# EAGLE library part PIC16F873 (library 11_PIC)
MICROCONTROLLER flash type
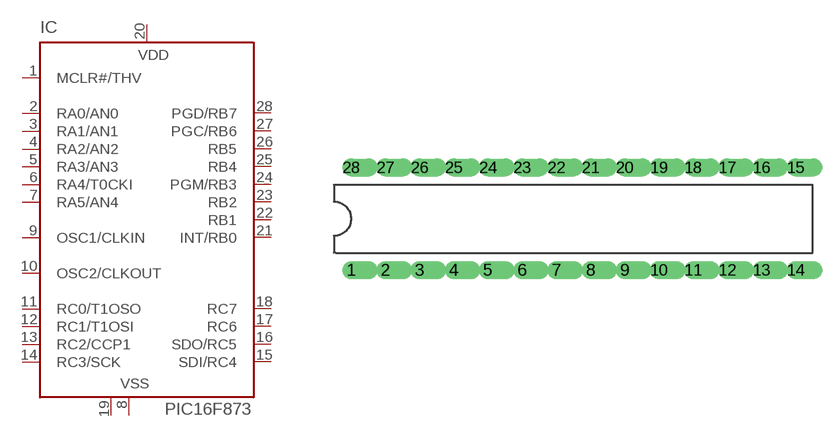
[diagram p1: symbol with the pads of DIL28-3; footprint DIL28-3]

Designator prefix IC

## PIC16F873  [DIL28-3]
1  MCLR#/THV  in
2  RA0/AN0
3  RA1/AN1
4  RA2/AN2
5  RA3/AN3
6  RA4/T0CKI
7  RA5/AN4
8  VSS  pwr
9  OSC1/CLKIN  in
10  OSC2/CLKOUT  out
11  RC0/T1OSO
12  RC1/T1OSI
13  RC2/CCP1
14  RC3/SCK
15  SDI/RC4
16  SDO/RC5
17  RC6
18  RC7
19  VSS  pwr
20  VDD  pwr
21  INT/RB0
22  RB1
23  RB2
24  PGM/RB3
25  RB4
26  RB5
27  PGC/RB6
28  PGD/RB7

## Footprint DIL28-3 (pad centres in mm)
drill 0.813 offset: 1 -16.51,-3.81; 2 -13.97,-3.81; 3 -11.43,-3.81; 4 -8.89,-3.81; 5 -6.35,-3.81; 6 -3.81,-3.81; 7 -1.27,-3.81; 8 1.27,-3.81; 9 3.81,-3.81; 10 6.35,-3.81; 11 8.89,-3.81; 12 11.43,-3.81; 13 13.97,-3.81; 14 16.51,-3.81; 15 16.51,3.81; 16 13.97,3.81; 17 11.43,3.81; 18 8.89,3.81; 19 6.35,3.81; 20 3.81,3.81; 21 1.27,3.81; 22 -1.27,3.81; 23 -3.81,3.81; 24 -6.35,3.81; 25 -8.89,3.81; 26 -11.43,3.81; 27 -13.97,3.81; 28 -16.51,3.81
